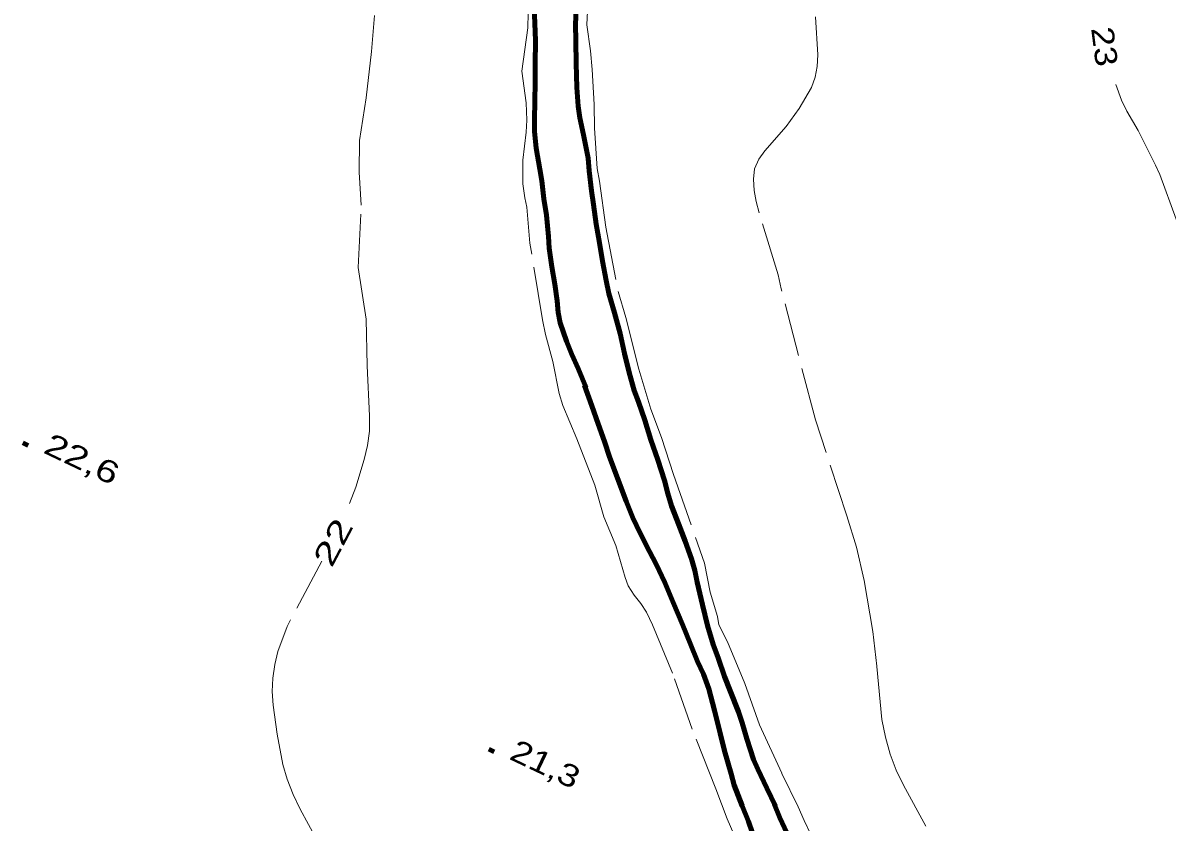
# Model space of a CAD drawing. Extents: x 356765 to 358572, y 5103174 to 5104650.
# Drawn here: x 357208.9 to 357286.2, y 5104106.3 to 5104160.3 of the extents above; entities that cross this region are included whole.
import ezdxf
from ezdxf.enums import TextEntityAlignment as Align

# ---------------------------------------------------------------- set-up
doc = ezdxf.new("R2010")
doc.units = 0
doc.header["$LTSCALE"] = 0.6
doc.linetypes.add('LONG_DASHED', pattern=[7.5, 6, -1.5])
for name, color, linetype, lineweight in [('2', 7, 'Continuous', 13), ('3', 7, 'Continuous', 140), ('4', 7, 'Continuous', 90)]:
    doc.layers.add(name, color=color, linetype=linetype, lineweight=lineweight)

msp = doc.modelspace()

# ---------------------------------------------------------------- linework, layer by layer
at = {"layer": '2', "linetype": 'LONG_DASHED'}
for points in [[(357257.39, 5104104.47), (357256.49, 5104106.51), (357255.73, 5104108.55), (357254.13, 5104112.58), (357252.81, 5104116.36), (357251.46, 5104119.63), (357251.04, 5104120.48), (357250.67, 5104121.07), (357250.21, 5104121.63), (357249.81, 5104122.26), (357249.6, 5104122.83), (357248.97, 5104125), (357248.16, 5104126.94), (357247.56, 5104129.07), (357246.34, 5104132.21), (357245.38, 5104134.46), (357245.15, 5104135.28), (357244.72, 5104137.44), (357244.21, 5104139.26), (357244.01, 5104140.26), (357243.17, 5104145.44), (357242.96, 5104147.88), (357242.82, 5104148.51), (357242.69, 5104149.44), (357242.69, 5104151.05), (357242.92, 5104152.93), (357242.95, 5104153.76), (357242.91, 5104154.92), (357242.63, 5104157.07), (357243.02, 5104160), (357243.07, 5104161.99)], [(357247.09, 5104161.57), (357247.01, 5104160.2), (357247.26, 5104158.45), (357247.38, 5104157.18), (357247.5, 5104154.82), (357247.52, 5104153.21), (357247.71, 5104150.49), (357247.87, 5104149.63), (357248.29, 5104146.51), (357249.12, 5104142.18), (357249.66, 5104140.42), (357250.53, 5104136.91), (357251.34, 5104134.22), (357252.07, 5104132.29), (357252.88, 5104129.79), (357254.96, 5104123.8), (357255.35, 5104121.84), (357255.85, 5104120.19), (357255.93, 5104119.63), (357256.52, 5104118.48), (357257.7, 5104115.67), (357258.69, 5104112.87), (357260.19, 5104109.59), (357261.31, 5104107.32), (357261.7, 5104106.4), (357262.82, 5104104.05)], [(357230.96, 5104127.84), (357231.39, 5104128.94), (357231.97, 5104130.82), (357232.18, 5104131.75), (357232.32, 5104132.73), (357232.33, 5104133.76), (357232.17, 5104137.15), (357232.09, 5104140.3), (357231.56, 5104143.8), (357231.76, 5104148), (357231.63, 5104150.23), (357231.65, 5104152.37), (357232.09, 5104155.27), (357232.46, 5104158.39), (357232.65, 5104160.83)], [(357269.94, 5104106.01), (357268.41, 5104108.79), (357267.92, 5104109.8), (357267.52, 5104110.88), (357267.21, 5104112.04), (357266.96, 5104113.23), (357266.62, 5104116.84), (357266.34, 5104119.19), (357265.77, 5104122.62), (357265.25, 5104124.88), (357264.6, 5104127.01), (357262.46, 5104133.49), (357260.15, 5104142.36), (357259.94, 5104143.3), (357258.66, 5104147.49), (357258.45, 5104148.25), (357258.33, 5104149), (357258.28, 5104149.76), (357258.35, 5104150.47), (357258.63, 5104151.12), (357259.04, 5104151.69), (357260.49, 5104153.32), (357261.36, 5104154.55), (357262.19, 5104155.95), (357262.45, 5104156.67), (357262.58, 5104157.38), (357262.63, 5104158.16), (357262.47, 5104160.73)], [(357229.09, 5104123.94), (357226.76, 5104119.53), (357226.13, 5104117.84), (357225.92, 5104116.94), (357225.78, 5104116.03), (357225.75, 5104115.13), (357225.82, 5104114.2), (357226.09, 5104112.25), (357226.47, 5104110.18), (357226.75, 5104109.19), (357227.15, 5104108.17), (357227.64, 5104107.16), (357228.75, 5104105.09)]]:
    msp.add_lwpolyline(points, dxfattribs=at)
at = {"layer": '2'}
msp.add_lwpolyline([(357295.51, 5104110.63), (357294.77, 5104111.63), (357294.25, 5104112.59), (357292.5, 5104117.55), (357291.44, 5104119.84), (357291.11, 5104120.67), (357290.83, 5104121.55), (357290.61, 5104122.53), (357290.46, 5104123.59), (357290.03, 5104129.38), (357289.88, 5104134.28), (357289.79, 5104135.51), (357289.44, 5104137.84), (357289.15, 5104138.92), (357288.41, 5104140.94), (357287.73, 5104143.05), (357287.32, 5104145.18), (357286.86, 5104147.05), (357285.74, 5104150.08), (357285.46, 5104150.72), (357284.28, 5104153.05), (357283.51, 5104154.37), (357283.15, 5104155.11), (357282.77, 5104156.16)], dxfattribs=at)
at = {"layer": '3'}
for p, q in [((357208.89, 5104131.93), (357209.25, 5104131.76)), ((357240.39, 5104111.22), (357240.75, 5104111.05))]:
    msp.add_line(p, q, dxfattribs=at)
at = {"layer": '4'}
for points in [[(357246.96, 5104135.65), (357246.43, 5104136.97), (357245.99, 5104137.9), (357245.64, 5104138.8), (357245.22, 5104140.05), (357245.07, 5104140.76), (357245.01, 5104141.53), (357244.86, 5104142.66), (357244.64, 5104143.84), (357244.47, 5104145.09), (357244.42, 5104145.88), (357244.28, 5104147.33), (357244.11, 5104148.43), (357243.98, 5104149.65), (357243.84, 5104150.43), (357243.59, 5104151.87), (357243.48, 5104152.98), (357243.47, 5104153.79), (357243.5, 5104155.04), (357243.51, 5104156.3), (357243.53, 5104157.55), (357243.54, 5104159.11), (357243.5, 5104160.3), (357243.44, 5104161.87)], [(357246.32, 5104161.7), (357246.25, 5104160.24), (357246.26, 5104159.09), (357246.3, 5104157.58), (357246.34, 5104155.95), (357246.42, 5104154.71), (357246.53, 5104153.91), (357246.78, 5104152.75), (357247.1, 5104151.19), (357247.18, 5104150.32), (357247.32, 5104148.98), (357247.46, 5104148.05), (357247.65, 5104146.72), (357247.87, 5104145.45), (357248.08, 5104144.21), (357248.31, 5104142.91), (357248.51, 5104142.04), (357248.89, 5104140.73), (357249.26, 5104139.34), (357249.56, 5104137.98), (357249.87, 5104136.7), (357250.22, 5104135.48), (357250.5, 5104134.7), (357250.93, 5104133.47), (357251.35, 5104132.13), (357251.81, 5104130.79), (357252.26, 5104129.38), (357252.48, 5104128.51), (357252.74, 5104127.68), (357253.2, 5104126.46), (357253.66, 5104125.29), (357254.09, 5104124.09), (357254.31, 5104123.3), (357254.47, 5104122.51), (357254.83, 5104120.99), (357255.18, 5104119.58), (357255.56, 5104118.3), (357255.88, 5104117.41), (357256.32, 5104116.13), (357256.71, 5104115.16), (357257.27, 5104113.76), (357257.52, 5104113.01), (357257.83, 5104111.92), (357258.27, 5104110.53), (357258.57, 5104109.87), (357259.19, 5104108.59), (357259.77, 5104107.37)], [(357256.77, 5104109.56), (357256.33, 5104111.11), (357256.03, 5104112.31), (357255.65, 5104113.85), (357255.25, 5104115.3), (357254.89, 5104116.29), (357254.5, 5104117.16), (357254.02, 5104118.33), (357253.48, 5104119.66), (357252.86, 5104121.15), (357252.28, 5104122.5), (357251.71, 5104123.73), (357251.24, 5104124.58), (357250.61, 5104125.82), (357250.13, 5104126.86), (357249.67, 5104128), (357249.08, 5104129.55), (357248.54, 5104130.99), (357248.2, 5104132.02), (357247.78, 5104133.22), (357247.36, 5104134.44), (357246.86, 5104135.81)], [(357258.43, 5104104.9), (357257.95, 5104106.34), (357257.52, 5104107.39), (357256.97, 5104108.8), (357256.77, 5104109.56)], [(357259.67, 5104107.53), (357260.06, 5104106.58), (357260.54, 5104105.58)]]:
    msp.add_lwpolyline(points, dxfattribs=at)

# ---------------------------------------------------------------- texts
at = {"layer": '2'}
for s, rotation, width, p in [('23', 277.389, 1.2, (357281.2703, 5104158.6364)), ('22', 62.137, 1.45, (357230.5183, 5104124.8645))]:
    msp.add_text(s, height=1.5, rotation=rotation, dxfattribs=dict(at, width=width)).set_placement(p, align=Align.CENTER)
at = {"layer": '3'}
for s, width, p in [('22,6   ', 1.35, (357210.19, 5104131.3)), ('21,3   ', 1.25, (357241.69, 5104110.59))]:
    msp.add_text(s, height=1.5, rotation=334.619, dxfattribs=dict(at, width=width)).set_placement(p)

doc.saveas('drawing.dxf')
